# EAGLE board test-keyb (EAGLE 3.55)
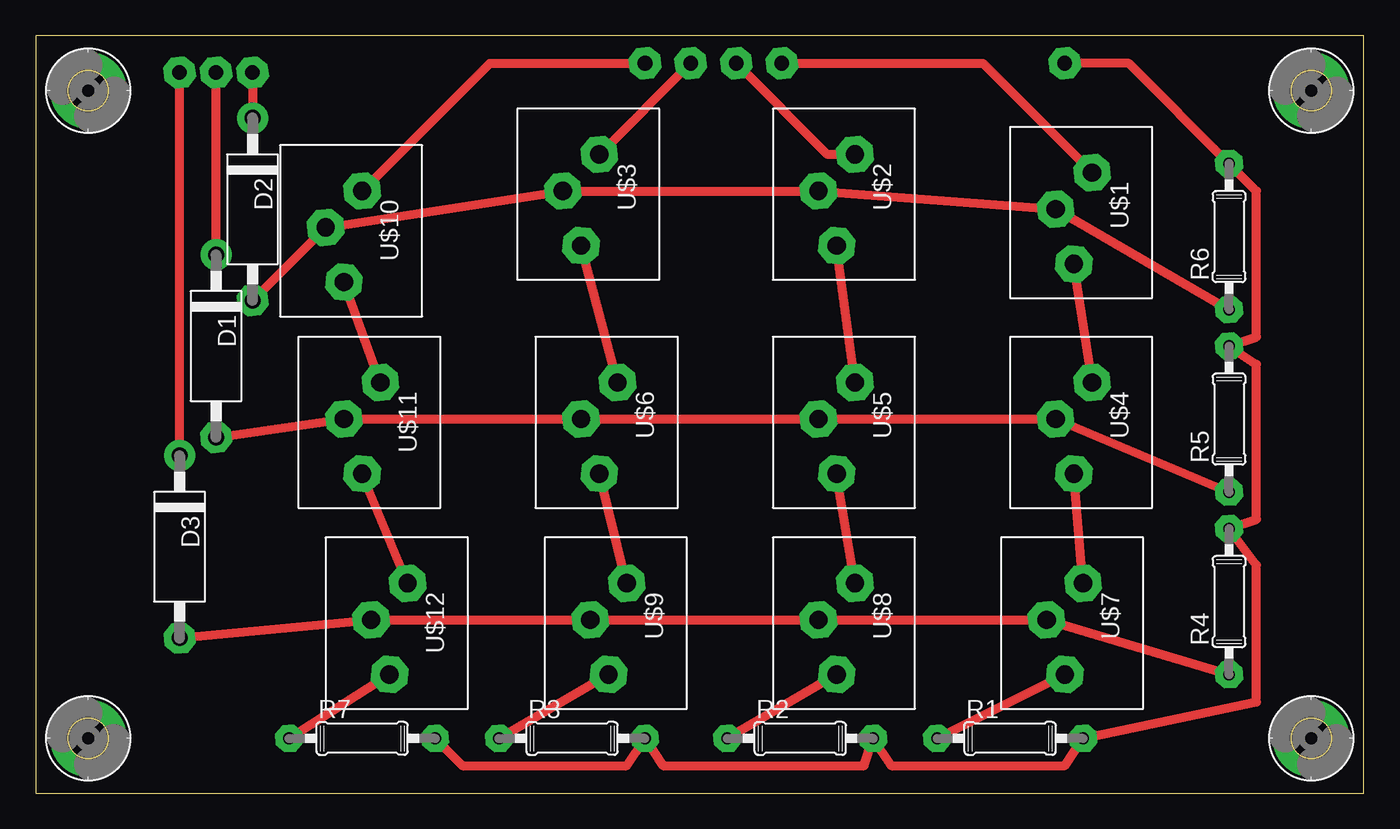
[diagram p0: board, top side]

Size 92.38 x 52.7 mm. Coordinates in mm from the lower left corner, seen from the top.
Outline: 0,0 92.38,0 92.38,52.7 0,52.7 0,0
Copper layers used: Top

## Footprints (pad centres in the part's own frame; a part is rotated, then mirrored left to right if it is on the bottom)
15-12 = drill 1.118 pad 2.159 round:  -6.35,0 | drill 1.118 pad 2.159 octagon:  6.35,0
2,8-P = drill 2.794 pad 5.334 round: 8 0,0
07/10B = drill 0.813 pad 1.905 octagon:  -5.08,0;  5.08,0
NDBTN = drill 1.27 pad 2.54 octagon:  3.175,-0.635;  -0.635,-1.905;  -3.175,0.635
D = drill 1.016 pad 2.184 octagon:  0,0

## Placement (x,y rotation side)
D1  1N821  [15-12]  12.54,31.11 270 top
D2  1N821  [15-12]  15.08,40.64 270 top
D3  1N821  [15-12]  9.99,17.14 270 top
PAD1  BO2,8P  [2,8-P]  3.64,48.89 270 top
PAD2  BO2,8P  [2,8-P]  3.64,3.8 270 top
PAD3  BO2,8P  [2,8-P]  88.73,48.89 270 top
PAD4  BO2,8P  [2,8-P]  88.73,3.8 270 top
R1  0204/5  [07/10B]  67.78,3.8 0 top
R2  0204/5  [07/10B]  53.18,3.8 0 top
R3  0204/5  [07/10B]  37.3,3.8 0 top
R4  0204/5  [07/10B]  83.02,13.33 90 top
R5  0204/5  [07/10B]  83.02,26.03 90 top
R6  0204/5  [07/10B]  83.02,38.73 90 top
R7  0204/5  [07/10B]  22.7,3.8 0 top
U$1  RUNDBTN  [NDBTN]  72.86,40 270 top
U$2  RUNDBTN  [NDBTN]  56.35,41.27 270 top
U$3  RUNDBTN  [NDBTN]  38.57,41.27 270 top
U$4  RUNDBTN  [NDBTN]  72.86,25.39 270 top
U$5  RUNDBTN  [NDBTN]  56.35,25.39 270 top
U$6  RUNDBTN  [NDBTN]  39.84,25.39 270 top
U$7  RUNDBTN  [NDBTN]  72.23,11.43 270 top
U$8  RUNDBTN  [NDBTN]  56.35,11.43 270 top
U$9  RUNDBTN  [NDBTN]  40.48,11.43 270 top
U$10  RUNDBTN  [NDBTN]  22.06,38.73 270 top
U$11  RUNDBTN  [NDBTN]  23.33,25.39 270 top
U$12  RUNDBTN  [NDBTN]  25.23,11.43 270 top
U$13  PAD  [D]  51.91,50.8 0 top
U$14  PAD  [D]  48.73,50.8 0 top
U$15  PAD  [D]  45.55,50.8 0 top
U$16  PAD  [D]  42.38,50.8 0 top
U$17  PAD  [D]  15.08,50.16 0 top
U$18  PAD  [D]  12.54,50.16 0 top
U$19  PAD  [D]  9.99,50.16 0 top
U$20  PAD  [D]  71.59,50.8 0 top

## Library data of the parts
D1-D3 = diode
PAD1-PAD4 = holes
R1-R7 = r
U$1-U$20 = buttons

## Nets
N$1: U$6. U$9.
N$2: R1. R2. R3. R4. R5. R6. R7. U$20.
N$3: D1. R5. U$4. U$5. U$6. U$11.
N$4: U$1. U$13.
N$5: U$1. U$4.
N$6: U$4. U$7.
N$7: R1. U$7.
N$8: U$2. U$14.
N$9: U$3. U$15.
N$10: U$10. U$16.
N$11: U$2. U$5.
N$12: D3. U$19.
N$13: U$3. U$6.
N$14: U$5. U$8.
N$15: U$10. U$11.
N$16: U$11. U$12.
N$17: R7. U$12.
N$18: R3. U$9.
N$19: R2. U$8.
N$20: D2. R6. U$1. U$2. U$3. U$10.
N$21: D1. U$18.
N$22: D2. U$17.
N$23: D3. R4. U$7. U$8. U$9. U$12.

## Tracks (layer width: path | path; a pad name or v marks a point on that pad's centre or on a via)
N$1
  Top 0.61: U$9. 39.2,22.22
N$2
  Top 0.61: R7. 29.68,1.9 41.11,1.9 R3. 43.65,1.9 57.62,1.9 R2. 59.52,1.9 71.59,1.9 R1. 84.92,6.35 84.92,15.87 R4. 84.92,19.04 84.92,29.84 R5. 84.92,31.75 84.92,41.91 R6. 76.03,50.8 U$20.
N$3
  Top 0.61: D1. 21.42,26.03 37.94,26.03 54.45,26.03 70.95,26.03 83.02,20.95
N$4
  Top 0.61: U$13. 65.88,50.8 U$1.
N$5
  Top 0.61: U$4. 72.23,36.83
N$6
  Top 0.61: U$7. 72.23,22.22
N$7
  Top 0.61: 62.7,3.8 71.59,8.25
N$8
  Top 0.61: U$2. 55.08,44.45 U$14.
N$9
  Top 0.61: U$3. U$15.
N$10
  Top 0.61: U$10. 31.59,50.8 U$16.
N$11
  Top 0.61: U$5. 55.72,38.1
N$12
  Top 0.61: 9.99,23.49 U$19.
N$13
  Top 0.61: U$6. 37.94,38.1
N$14
  Top 0.61: U$8. 55.72,22.22
N$15
  Top 0.61: U$11. 21.42,35.56
N$16
  Top 0.61: U$12. 22.7,22.22
N$17
  Top 0.61: 17.62,3.8 24.6,8.25
N$18
  Top 0.61: 32.22,3.8 39.84,8.25
N$19
  Top 0.61: 48.09,3.8 55.72,8.25
N$20
  Top 0.61: 83.02,33.65 70.95,40.64 54.45,41.91 36.66,41.91 20.16,39.37 D2.
N$21
  Top 0.61: 12.54,37.46 U$18.
N$22
  Top 0.61: U$17. 15.08,46.99
N$23
  Top 0.61: D3. 23.33,12.06 38.57,12.06 54.45,12.06 70.32,12.06 83.02,8.25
